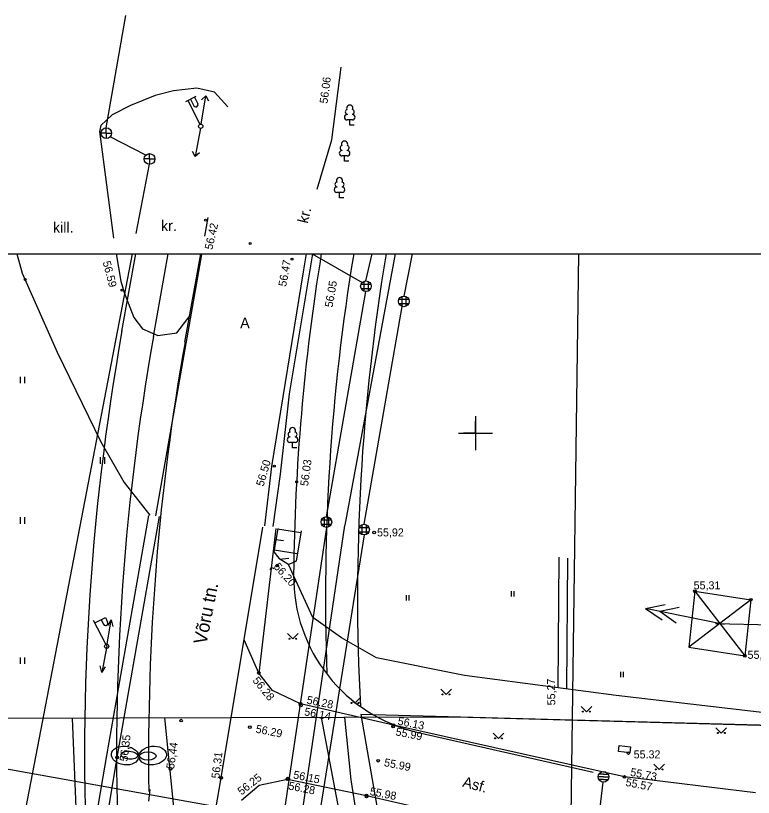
# Model space of a CAD drawing. Extents: x 9156 to 9809, y 2728 to 4000.
# Drawn here: x 9406.9 to 9476, y 3915.9 to 3989.1 of the extents above; entities that cross this region are included whole.
import ezdxf

# ---------------------------------------------------------------- set-up
doc = ezdxf.new("R2010")
doc.units = 0
for name, color, linetype in [('Level 1', 7, 'Continuous'), ('Level 11', 7, 'Continuous'), ('Level 12', 7, 'Continuous'), ('Level 14', 7, 'Continuous'), ('Level 15', 7, 'Continuous'), ('Level 17', 7, 'Continuous'), ('Level 18', 7, 'Continuous'), ('Level 24', 7, 'Continuous'), ('Level 26', 7, 'Continuous'), ('Level 41', 7, 'Continuous'), ('Level 54', 7, 'Continuous'), ('Level 56', 7, 'Continuous'), ('Level 58', 7, 'Continuous'), ('Level 59', 7, 'Continuous'), ('Level 6', 7, 'Continuous'), ('Level 61', 7, 'Continuous'), ('Level 63', 7, 'Continuous'), ('Level 7', 7, 'Continuous'), ('Level 8', 7, 'Continuous')]:
    doc.layers.add(name, color=color, linetype=linetype)

# ---------------------------------------------------------------- blocks, each defined once
blk = doc.blocks.new('KKOL')
at = {"layer": 'Level 58'}
for p, q in [((0, 1.59349), (0, -1.5935)), ((-1.5935, 0), (1.59349, 0))]:
    blk.add_line(p, q, dxfattribs=at)
blk = doc.blocks.new('KVPOST')
at = {"layer": 'Level 11'}
for p, q in [((0, 0.2), (0, 2.7)), ((0, 2.444), (1.1, 2.444)), ((0.655, 2.449), (0.65, 1.971)), ((1.1, 2.444), (1.094, 1.965))]:
    blk.add_line(p, q, dxfattribs=at)
blk.add_circle((0, 0), 0.2, dxfattribs=at)
blk.add_arc((0.872, 1.968), 0.222, 179.31175, 359.31175, dxfattribs=at)
blk = doc.blocks.new('KMNOOL')
at = {"layer": 'Level 12'}
for p, q in [((0, 0), (2.5, -0.006)), ((2.5, -0.006), (1.926, 0.242)), ((2.5, -0.006), (1.925, -0.251))]:
    blk.add_line(p, q, dxfattribs=at)
blk = doc.blocks.new('WKNOOL')
at = {"layer": 'Level 26'}
for p, q in [((3.073, 0), (2.212, 0.37)), ((3.75, 0), (2.889, 0.37)), ((0, 0), (3.75, 0)), ((3.073, 0), (2.212, -0.37)), ((3.75, 0), (2.889, -0.37))]:
    blk.add_line(p, q, dxfattribs=at)
blk = doc.blocks.new('HEIN')
at = {"layer": 'Level 41'}
for p, q in [((-0.121, 0.039), (-0.121, 0.539)), ((0.129, 0.039), (0.129, 0.539))]:
    blk.add_line(p, q, dxfattribs=at)
blk = doc.blocks.new('RESKAE')
at = {"layer": 'Level 24'}
for p, q in [((0, 0), (-0.5, 0)), ((0, 0.25), (-0.433, 0.25)), ((0, 0.25), (0.433, 0.25)), ((0, 0), (0.5, 0)), ((0, -0.25), (-0.433, -0.25)), ((0, -0.25), (0.433, -0.25))]:
    blk.add_line(p, q, dxfattribs=at)
blk.add_circle((0, 0), 0.5, dxfattribs=at)
blk = doc.blocks.new('MURU')
at = {"layer": 'Level 41'}
for p, q in [((-0.5, 0.5), (0, 0)), ((0, 0), (0.5, 0.5))]:
    blk.add_line(p, q, dxfattribs=at)
for centre in [(-0.32, 0.015), (0.32, 0.014)]:
    blk.add_circle(centre, 0.0466, dxfattribs=at)
blk = doc.blocks.new('KPUNKT')
at = {"layer": 'Level 59'}
blk.add_circle((0, 0), 0.125, dxfattribs=at)
blk = doc.blocks.new('KRTRIS')
at = {"layer": 'Level 61'}
for q in [(0, 1.125), (-1.125, 0), (1.125, 0), (0, -1.125)]:
    blk.add_line((0, 0), q, dxfattribs=at)

msp = doc.modelspace()

# ---------------------------------------------------------------- linework, layer by layer
at = {"layer": 'Level 1'}
for p, q in [((9406.13, 3923.27), (9448.16, 3923.4)), ((9406.13, 3923.27), (9448.16, 3923.4)), ((9448.16, 3923.4), (9528.25, 3921.24)), ((9448.16, 3923.4), (9528.25, 3921.24))]:
    msp.add_line(p, q, dxfattribs=at)
at = {"layer": 'Level 12'}
msp.add_line((9413.577, 3892.144), (9412.2, 3923.289), dxfattribs=at)
at = {"layer": 'Level 14'}
msp.add_line((9421.781, 3914.32), (9420.882, 3923.316), dxfattribs=at)
at = {"layer": 'Level 15'}
for p, q in [((9438.337, 3917.498), (9437.733, 3923.36)), ((9440.149, 3905.714), (9438.337, 3917.498))]:
    msp.add_line(p, q, dxfattribs=at)
at = {"layer": 'Level 17'}
for p, q in [((9416.853, 3959.567), (9418.143, 3966.797)), ((9419.807, 3959.041), (9421.19, 3966.797)), ((9443.805, 3880.319), (9435.548, 3923.361))]:
    msp.add_line(p, q, dxfattribs=at)
for centre, radius, start, end in [((9631.829, 3934.713), 195.9, 170.57368, 182.13711), ((9631.829, 3934.713), 192.9, 170.42572, 183.07113), ((9639.344, 3919.894), 226, 169.88959, 183.36818), ((9639.344, 3919.894), 223, 169.88959, 182.77512)]:
    msp.add_arc(centre, radius, start, end, dxfattribs=at)
at = {"layer": 'Level 18'}
for p, q in [((9422.76, 3958.514), (9424.237, 3966.797)), ((9444.624, 3921.945), (9461.022, 3918.231)), ((9419.474, 3916.59), (9419.328, 3915.491))]:
    msp.add_line(p, q, dxfattribs=at)
for centre, radius, start, end in [((9631.829, 3934.713), 198.9, 170.71713, 179.42006), ((9639.344, 3919.894), 220, 169.88959, 180.90615), ((9447.938, 3936.574), 15, 179.42006, 257.23634)]:
    msp.add_arc(centre, radius, start, end, dxfattribs=at)
at = {"layer": 'Level 54'}
for p, q in [((9415.383, 3978.604), (9417.209, 3989.122)), ((9436.514, 3977.468), (9437.408, 3984.294)), ((9421.693, 3982.067), (9419.958, 3981.632)), ((9423.861, 3982.316), (9421.693, 3982.067)), ((9425.534, 3981.943), (9423.861, 3982.316)), ((9426.772, 3980.576), (9425.534, 3981.943)), ((9419.958, 3981.632), (9417.666, 3980.7)), ((9422.839, 3981.076), (9423.82, 3981.573)), ((9423.017, 3981.167), (9424.146, 3978.936)), ((9423.285, 3981.302), (9423.601, 3980.678)), ((9423.641, 3981.483), (9423.958, 3980.858)), ((9424.269, 3978.955), (9424.716, 3981.618)), ((9424.317, 3981.239), (9424.716, 3981.618)), ((9424.716, 3981.618), (9424.969, 3981.13)), ((9417.666, 3980.7), (9415.932, 3979.831)), ((9415.932, 3979.831), (9414.879, 3978.837)), ((9437.952, 3979.884), (9437.952, 3979.852)), ((9438.452, 3979.884), (9438.452, 3979.852)), ((9414.879, 3978.837), (9414.755, 3978.277)), ((9438.452, 3979.352), (9437.952, 3979.352)), ((9438.202, 3978.852), (9438.202, 3979.352)), ((9438.602, 3978.852), (9438.202, 3978.852)), ((9414.755, 3978.277), (9416.056, 3968.275)), ((9415.383, 3978.104), (9414.883, 3978.104)), ((9415.383, 3978.104), (9415.383, 3978.604)), ((9415.383, 3978.104), (9415.883, 3978.104)), ((9415.383, 3978.104), (9415.383, 3977.604)), ((9424.2, 3978.561), (9423.709, 3975.906)), ((9419.086, 3976.044), (9415.737, 3977.75)), ((9435.14, 3972.872), (9436.514, 3977.468)), ((9419.44, 3975.69), (9419.44, 3976.19)), ((9423.709, 3975.906), (9423.464, 3976.398)), ((9424.115, 3976.278), (9423.709, 3975.906)), ((9437.471, 3976.505), (9437.471, 3976.473)), ((9437.971, 3975.973), (9437.471, 3975.973)), ((9437.721, 3975.473), (9437.721, 3975.973)), ((9437.971, 3976.505), (9437.971, 3976.473)), ((9418.191, 3968.691), (9419.44, 3975.19)), ((9419.44, 3975.69), (9418.94, 3975.69)), ((9419.44, 3975.69), (9419.94, 3975.69)), ((9419.44, 3975.69), (9419.44, 3975.19)), ((9438.121, 3975.473), (9437.721, 3975.473)), ((9436.99, 3973.091), (9436.99, 3973.059)), ((9437.49, 3973.091), (9437.49, 3973.059)), ((9437.49, 3972.559), (9436.99, 3972.559)), ((9437.24, 3972.059), (9437.24, 3972.559)), ((9437.64, 3972.059), (9437.24, 3972.059)), ((9424.904, 3970.216), (9424.593, 3968.445)), ((9402.671, 3887.904), (9417.828, 3966.797)), ((9407.003, 3966.797), (9407.509, 3964.983)), ((9416.305, 3966.797), (9416.737, 3964.237)), ((9424.294, 3966.745), (9419.994, 3942.26)), ((9433.868, 3965.115), (9434.143, 3966.797)), ((9434.689, 3966.797), (9439.37, 3964.114)), ((9442.453, 3966.797), (9437.755, 3941.359)), ((9439.723, 3964.261), (9440.293, 3966.797)), ((9443.304, 3962.824), (9444.07, 3966.797)), ((9458.61, 3888.477), (9459.675, 3966.797)), ((9407.509, 3964.983), (9410.792, 3957.59)), ((9430.911, 3946.879), (9433.868, 3965.115)), ((9416.737, 3964.237), (9417.047, 3963.181)), ((9439.523, 3964.219), (9439.523, 3963.302)), ((9439.923, 3964.219), (9439.923, 3963.302)), ((9439.265, 3963.961), (9440.182, 3963.961)), ((9439.265, 3963.561), (9440.182, 3963.561)), ((9417.047, 3963.181), (9417.976, 3960.82)), ((9436.011, 3942.162), (9439.723, 3963.261)), ((9443.074, 3962.804), (9443.074, 3961.887)), ((9443.474, 3962.804), (9443.474, 3961.887)), ((9442.815, 3962.546), (9443.732, 3962.546)), ((9442.815, 3962.146), (9443.732, 3962.146)), ((9439.541, 3941.452), (9443.122, 3961.866)), ((9417.976, 3960.82), (9418.781, 3959.764)), ((9422.003, 3959.391), (9423.242, 3961.006)), ((9418.781, 3959.764), (9420.206, 3959.143)), ((9420.206, 3959.143), (9422.003, 3959.391)), ((9410.792, 3957.59), (9414.875, 3949.174)), ((9407.32, 3955.283), (9407.32, 3954.663)), ((9407.726, 3955.271), (9407.726, 3954.663)), ((9450, 3951.25), (9450, 3948.75)), ((9432.591, 3949.657), (9432.591, 3949.625)), ((9433.091, 3949.657), (9433.091, 3949.625)), ((9448.75, 3950), (9451.25, 3950)), ((9414.875, 3949.174), (9417.043, 3945.384)), ((9433.091, 3949.125), (9432.591, 3949.125)), ((9432.841, 3948.625), (9432.841, 3949.125)), ((9433.241, 3948.625), (9432.841, 3948.625)), ((9414.796, 3947.752), (9414.796, 3947.131)), ((9415.202, 3947.74), (9415.202, 3947.131)), ((9430.228, 3941.305), (9430.911, 3946.879)), ((9417.043, 3945.384), (9419.475, 3942.308)), ((9415.424, 3919.779), (9419.363, 3942.272)), ((9416.409, 3919.606), (9420.36, 3942.171)), ((9407.32, 3942.131), (9407.32, 3941.511)), ((9407.726, 3942.12), (9407.726, 3941.511)), ((9435.553, 3941.862), (9436.469, 3941.862)), ((9435.553, 3941.462), (9436.469, 3941.462)), ((9435.811, 3942.12), (9435.811, 3941.204)), ((9436.211, 3942.12), (9436.211, 3941.204)), ((9426.142, 3917.687), (9430.051, 3941.188)), ((9431.289, 3941.063), (9429.687, 3927.515)), ((9436.011, 3941.162), (9430.809, 3906.242)), ((9431.443, 3941.029), (9433.618, 3940.677)), ((9431.927, 3902.125), (9437.754, 3941.348)), ((9439.082, 3941.152), (9439.999, 3941.152)), ((9439.082, 3940.752), (9439.999, 3940.752)), ((9439.341, 3941.411), (9439.341, 3940.494)), ((9439.741, 3941.411), (9439.741, 3940.494)), ((9431.283, 3940.042), (9432.006, 3939.925)), ((9439.541, 3940.452), (9433.953, 3905.503)), ((9431.124, 3939.055), (9433.284, 3938.705)), ((9431.568, 3938.273), (9432.48, 3937.699)), ((9431.631, 3938.193), (9432.483, 3938.286)), ((9457.788, 3938.376), (9457.693, 3926.133)), ((9458.617, 3938.292), (9458.522, 3926.025)), ((9470.558, 3935.192), (9469.978, 3929.927)), ((9470.558, 3935.192), (9475.219, 3929.122)), ((9475.799, 3934.386), (9469.978, 3929.927)), ((9429.687, 3927.515), (9428.291, 3930.609)), ((9469.978, 3929.927), (9475.219, 3929.122)), ((9407.32, 3928.98), (9407.32, 3928.36)), ((9407.726, 3928.969), (9407.726, 3928.36)), ((9414.137, 3912.205), (9415.423, 3919.774)), ((9415.397, 3913.645), (9416.409, 3919.606)), ((9461.91, 3917.301), (9459.956, 3900.532))]:
    msp.add_line(p, q, dxfattribs=at)
for points in [[(9434.719, 3966.797), (9432.532, 3953.671), (9431.676, 3946.155), (9430.991, 3941.234)], [(9431.446, 3941.047), (9431.093, 3938.866), (9431.568, 3938.273)], [(9433.643, 3940.824), (9433.165, 3938.004), (9432.48, 3937.699)], [(9490.503, 3922.595), (9484.61, 3922.9), (9463.175, 3925.42), (9448.951, 3927.271), (9440.713, 3928.951), (9437.435, 3930.799), (9434.745, 3932.731), (9432.475, 3937.688)], [(9470.558, 3935.192), (9475.799, 3934.386), (9475.219, 3929.122)], [(9463.95, 3917.775), (9442.302, 3922.629), (9433.576, 3924.621), (9430.952, 3925.885), (9429.687, 3927.515)], [(9415.997, 3832.136), (9418.853, 3854.304), (9418.853, 3854.304), (9418.027, 3862.261), (9417.976, 3870.031), (9426.142, 3917.687)], [(9428.052, 3915.601), (9429.725, 3917.012), (9432.375, 3917.571), (9439.765, 3916.028), (9446.144, 3914.564), (9448.243, 3913.268), (9450.022, 3910.266), (9453.083, 3899.783), (9455.587, 3890.791), (9454.937, 3890.396), (9455.145, 3889.508), (9455.861, 3889.464), (9459.478, 3877.013), (9463.895, 3860.759), (9466.082, 3852.651)], [(9476.224, 3916.283), (9463.95, 3917.775)]]:
    msp.add_lwpolyline(points, dxfattribs=at)
msp.add_lwpolyline([(9463.469, 3920.728), (9464.522, 3920.586), (9464.447, 3920.031), (9463.394, 3920.173)], close=True, dxfattribs=at)
for centre, radius in [((9424.236, 3978.758), 0.2), ((9415.383, 3978.104), 0.5), ((9419.44, 3975.69), 0.5), ((9424.686, 3969.959), 0.0909), ((9428.873, 3967.768), 0.0909), ((9432.788, 3966.307), 0.0909), ((9407.78, 3964.386), 0.0909), ((9439.723, 3963.761), 0.5), ((9416.857, 3963.386), 0.0909), ((9443.274, 3962.346), 0.5), ((9431.134, 3946.9), 0.0909), ((9433.228, 3945.439), 0.0909), ((9436.011, 3941.662), 0.5), ((9439.541, 3940.952), 0.5), ((9440.481, 3940.693), 0.125), ((9431.403, 3937.577), 0.125), ((9470.558, 3935.192), 0.125), ((9475.799, 3934.386), 0.125), ((9475.219, 3929.122), 0.125), ((9416.409, 3919.606), 0.125), ((9421.396, 3918.529), 0.125), ((9426.142, 3917.687), 0.125)]:
    msp.add_circle(centre, radius, dxfattribs=at)
for centre, radius, start, end in [((9423.779, 3980.768), 0.2, 206.78909, 26.91049), ((9438.002, 3980.102), 0.224, 105.2441, 257.07903), ((9438.202, 3980.452), 0.292, 332.5799, 207.4201), ((9438.402, 3980.102), 0.224, 282.92097, 74.7559), ((9437.952, 3979.602), 0.25, 90.00001, 270), ((9438.452, 3979.602), 0.25, 270, 89.99999), ((9437.721, 3977.073), 0.292, 332.5799, 207.4201), ((9437.521, 3976.723), 0.224, 105.2441, 257.07903), ((9437.921, 3976.723), 0.224, 282.92097, 74.7559), ((9437.471, 3976.223), 0.25, 90.00001, 270), ((9437.971, 3976.223), 0.25, 270, 89.99999), ((9437.24, 3973.659), 0.292, 332.5799, 207.4201), ((9436.99, 3972.809), 0.25, 90.00001, 270), ((9437.04, 3973.309), 0.224, 105.2441, 257.07903), ((9437.44, 3973.309), 0.224, 282.92097, 74.7559), ((9437.49, 3972.809), 0.25, 270, 89.99999), ((9432.841, 3950.225), 0.292, 332.5799, 207.4201), ((9432.591, 3949.375), 0.25, 90.00001, 270), ((9432.641, 3949.875), 0.224, 105.2441, 257.07903), ((9433.041, 3949.875), 0.224, 282.92097, 74.7559), ((9433.091, 3949.375), 0.25, 270, 89.99999), ((9430.931, 3937.139), 0.228, 41.71437, 156.42847)]:
    msp.add_arc(centre, radius, start, end, dxfattribs=at)
at = {"layer": 'Level 56'}
for p, q in [((9416.853, 3959.567), (9418.143, 3966.797)), ((9419.807, 3959.041), (9421.19, 3966.797)), ((9422.76, 3958.514), (9424.237, 3966.797)), ((9444.624, 3921.945), (9461.022, 3918.231)), ((9419.474, 3916.59), (9419.328, 3915.491))]:
    msp.add_line(p, q, dxfattribs=at)
for centre, radius, start, end in [((9631.829, 3934.713), 198.9, 170.71713, 179.42006), ((9631.829, 3934.713), 195.9, 170.57368, 182.13711), ((9631.829, 3934.713), 192.9, 170.42572, 183.07113), ((9639.344, 3919.894), 226, 169.88959, 183.36818), ((9639.344, 3919.894), 223, 169.88959, 182.77512), ((9639.344, 3919.894), 220, 169.88959, 180.90615), ((9447.938, 3936.574), 15, 179.42006, 257.23634)]:
    msp.add_arc(centre, radius, start, end, dxfattribs=at)
at = {"layer": 'Level 6'}
msp.add_line((9769.71, 3853.431), (9292.325, 3938.851), dxfattribs=at)
at = {"layer": 'Level 63'}
msp.add_lwpolyline([(9275.527, 3966.797), (9801.617, 3966.797), (9801.617, 3329.636), (9275.527, 3329.636)], close=True, dxfattribs=at)
at = {"layer": 'Level 7'}
for p, q in [((9528.25, 3921.24), (9439.242, 3923.641)), ((9439.242, 3923.641), (9446.918, 3879.882))]:
    msp.add_line(p, q, dxfattribs=at)
at = {"layer": 'Level 8'}
for centre, major_axis, ratio in [((9417.142, 3919.781), (1.285, -0.15), 0.674652), ((9417.142, 3919.781), (1.285, -0.15), 0.674652), ((9417.142, 3919.781), (1.285, -0.15), 0.674652), ((9417.142, 3919.781), (1.285, -0.15), 0.674652), ((9417.537, 3919.817), (0.774, -0.072), 0.486914), ((9417.537, 3919.817), (0.774, -0.072), 0.486914), ((9417.537, 3919.817), (0.774, -0.072), 0.486914), ((9417.537, 3919.817), (0.774, -0.072), 0.486914), ((9419.734, 3919.781), (-1.285, -0.15), 0.674652), ((9419.734, 3919.781), (-1.285, -0.15), 0.674652), ((9419.734, 3919.781), (-1.285, -0.15), 0.674652), ((9419.734, 3919.781), (-1.285, -0.15), 0.674652), ((9419.274, 3919.737), (-0.778, 0.002), 0.486914), ((9419.274, 3919.737), (-0.778, 0.002), 0.486914), ((9419.274, 3919.737), (-0.778, 0.002), 0.486914), ((9419.274, 3919.737), (-0.778, 0.002), 0.486914)]:
    msp.add_ellipse(centre, major_axis=major_axis, ratio=ratio, dxfattribs=at)

# ---------------------------------------------------------------- block references
at = {"layer": 'Level 54'}
for name, p in [('KKOL', (9450, 3950)), ('KRTRIS', (9450, 3950)), ('HEIN', (9453.481, 3934.645)), ('HEIN', (9443.648, 3934.277)), ('MURU', (9432.867, 3930.71)), ('KPUNKT', (9429.687, 3927.515)), ('HEIN', (9463.746, 3927.074)), ('MURU', (9447.225, 3925.493)), ('KPUNKT', (9433.576, 3924.621)), ('KPUNKT', (9433.625, 3924.463)), ('MURU', (9438.69, 3924.69)), ('MURU', (9460.378, 3923.887)), ('KPUNKT', (9422.39, 3923.054)), ('KPUNKT', (9428.839, 3922.439)), ('KPUNKT', (9442.269, 3922.505)), ('KPUNKT', (9442.302, 3922.629)), ('MURU', (9473.029, 3921.88)), ('MURU', (9452.145, 3921.379)), ('KPUNKT', (9464.314, 3920.014)), ('KPUNKT', (9440.871, 3919.299)), ('MURU', (9467.205, 3918.469)), ('RESKAE', (9461.991, 3917.789)), ('KPUNKT', (9432.375, 3917.571)), ('KPUNKT', (9432.421, 3917.627)), ('KPUNKT', (9463.95, 3917.775)), ('KPUNKT', (9439.765, 3916.028)), ('KPUNKT', (9439.787, 3915.927))]:
    msp.add_blockref(name, p, dxfattribs=at)
for name, p, xscale, yscale, rotation in [('WKNOOL', (9473.281, 3932.077), 2.0000000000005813, 1.9999999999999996, 168.55658700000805), ('KVPOST', (9415.419, 3930.026), 1.0000020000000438, 1.0000020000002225, 26.849865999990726), ('WKNOOL', (9472.489, 3932.167), 2.000000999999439, 2.000000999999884, -1.4791960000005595)]:
    msp.add_blockref(name, p, dxfattribs=dict(at, xscale=xscale, yscale=yscale, rotation=rotation))
for rotation in [80.49043800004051, -100.47537699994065]:
    msp.add_blockref('KMNOOL', (9415.419, 3930.026), dxfattribs=dict(at, rotation=rotation))

# ---------------------------------------------------------------- texts
for s, height, rotation, p in [('56.06', 0.75, 82.42695, (9436.11, 3980.846)), ('kr.', 1, 76.50188, (9434.266, 3969.592)), ('56.42', 0.75, 77.16894, (9425.318, 3967.136)), ('56.59', 0.75, 284.49399, (9415.038, 3966.026)), ('56.47', 0.75, 79.45291, (9432.234, 3963.685)), ('56.05', 0.75, 80.16216, (9436.588, 3961.738)), ('56.50', 0.75, 73.85454, (9430.12, 3944.957)), ('56.03', 0.75, 82.25696, (9434.292, 3944.993)), (' 56,20', 0.75, 311.2831, (9430.834, 3937.648)), ('Võru tn.', 1.25, 78.83196, (9424.76, 3930.124)), ('56.28', 0.75, 309.08009, (9429.05, 3926.785)), (' 55,27', 0.75, 90.83388, (9457.477, 3924.212)), ('56.28', 0.75, 348.78288, (9434.119, 3924.655)), ('56.14', 0.75, 348.78288, (9433.893, 3923.558)), ('56.13', 0.75, 348.78288, (9442.651, 3922.678)), ('56.29', 0.75, 348.78288, (9429.339, 3921.939)), ('55.99', 0.75, 348.78288, (9442.458, 3921.678)), (' 56,35', 0.75, 83.09891, (9417.334, 3918.916)), (' 56,44', 0.75, 81.87278, (9421.692, 3918.204)), (' 56,31', 0.75, 82.89268, (9425.935, 3917.311)), ('55.99', 0.75, 348.78288, (9441.371, 3918.799)), ('56.25', 0.75, 37.88631, (9428.051, 3916.027)), ('56.15', 0.75, 348.78288, (9432.861, 3917.64)), ('55.73', 0.75, 348.78288, (9464.446, 3917.892)), ('56.28', 0.75, 348.78288, (9432.409, 3916.608)), ('Asf.', 1, 344.75394, (9448.707, 3916.88)), ('55.57', 0.75, 348.78288, (9464.011, 3916.946)), ('55.98', 0.75, 348.78288, (9440.033, 3916.091))]:
    msp.add_text(s, height=height, rotation=rotation, dxfattribs=at).set_placement(p)
for s, height, p in [('kill.', 1, (9410.384, 3968.775)), ('kr.', 1, (9420.51, 3968.936)), ('A', 1, (9427.932, 3959.823)), (' 55,92', 0.75, (9440.481, 3940.318)), (' 55,31', 0.75, (9470.155, 3935.36)), (' 55,20', 0.75, (9475.21, 3928.846)), ('55.32', 0.75, (9464.814, 3919.514))]:
    msp.add_text(s, height=height, dxfattribs=at).set_placement(p)

doc.saveas('drawing.dxf')
